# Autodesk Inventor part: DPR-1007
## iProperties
Created: 2004-11
Part Number: DPR-1007
Cost Center: 0 lbmass
Document SubType Name: Modeling
Designer: busseym
Manufacturer: Standard
Standards Organization: Custom
Stock Number: DPR-1007
Density: 1 g/cm^3
CAGE: 1LJX3
Dept. ID: Product Design
Description #2: ---
Finish #1: ---
Finish #2: ---
Material ID: ---
Project Number: ---
Author: busseym
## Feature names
1. Extrusion1
2. Extrusion2
3. Extrusion4
4. Circular Pattern1
5. Mirror1
6. Extrusion3
7. Mirror2
